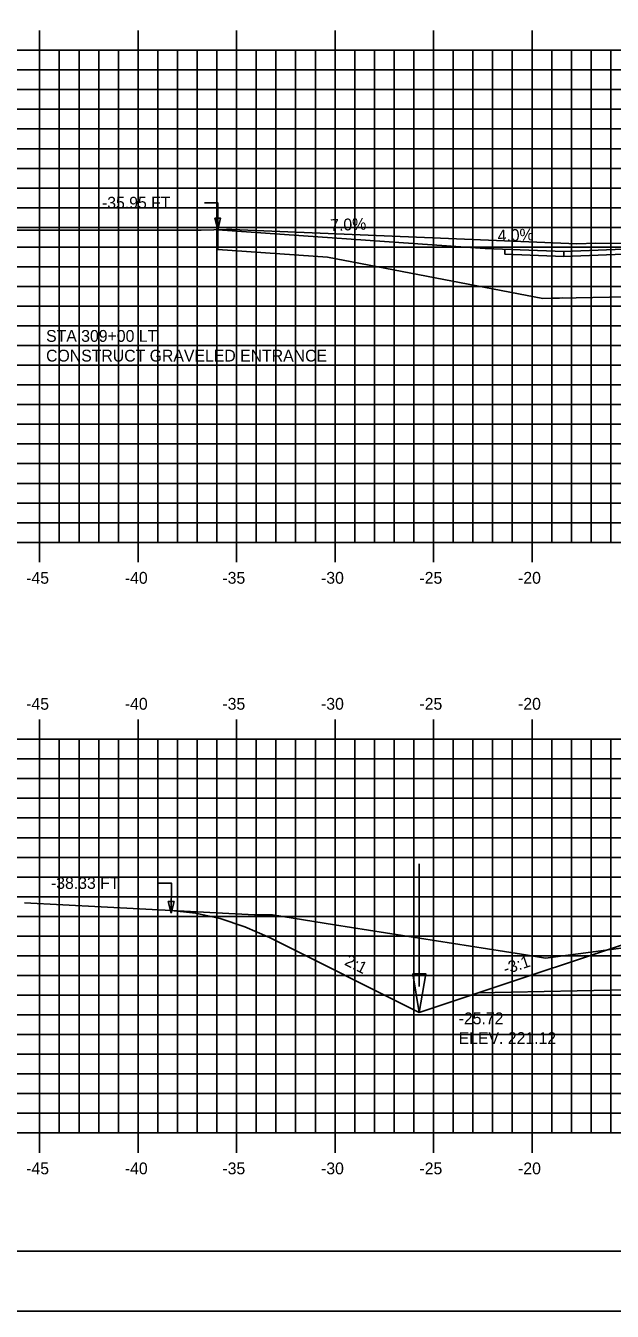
# Model space of a CAD drawing. Extents: x 1137876 to 1138046, y 608981 to 609091.
# Drawn here: x 1137913.5 to 1137943.2, y 608981.3 to 609046.6 of the extents above; entities that cross this region are included whole.
import ezdxf

# ---------------------------------------------------------------- set-up
doc = ezdxf.new("R2010")
doc.units = 0
for name, color, linetype in [('ANNOTATION', 7, 'Continuous'), ('BORDER', 7, 'Continuous'), ('D_Drainage_Ditch_Line', 7, 'Continuous'), ('D_Roadway_Edge_Shoulder', 7, 'Continuous'), ('D_Roadway_SlopeLines', 7, 'Continuous'), ('D_Roadway_SubGrade', 7, 'Continuous'), ('D_Text_Standard', 7, 'Continuous'), ('H_V ANNOTATION', 7, 'Continuous'), ('MAJOR', 7, 'Continuous'), ('MINOR', 7, 'Continuous'), ('PLOT BOUNDARY', 7, 'Continuous'), ('S_Roadway_Centerline', 7, 'Continuous')]:
    doc.layers.add(name, color=color, linetype=linetype)

msp = doc.modelspace()

# ---------------------------------------------------------------- linework, layer by layer
msp.add_lwpolyline([(1137920.838, 609001.638), (1137922.088, 609001.503), (1137923.338, 609001.228), (1137924.588, 609000.813), (1137925.838, 609000.258), (1137933.441, 608996.457), (1137936.441, 608997.457), (1137944.165, 609000.031), (1137944.166, 609000.031), (1137948.166, 609000.191), (1137959.166, 609000.411), (1137970.166, 609000.191), (1137977.166, 608999.911), (1137984.698, 608997.4), (1137989.882, 608995.673), (1137996.551, 608999.007), (1137997.801, 608999.558), (1137999.051, 608999.962), (1138000.301, 609000.217), (1138001.551, 609000.325)])
at = {"layer": 'ANNOTATION'}
for p, q in [((1137923.214, 609036.215), (1137923.214, 609035.215)), ((1137923.214, 609035.215), (1137928.788, 609034.825)), ((1137940.788, 609035.105), (1137936.788, 609035.265)), ((1137940.788, 609034.855), (1137937.79, 609034.975))]:
    msp.add_line(p, q, dxfattribs=at)
for points in [[(1137936.788, 609035.265), (1137935.788, 609035.335), (1137923.214, 609036.215)], [(1137940.722, 609032.751), (1137939.722, 609032.731), (1137928.788, 609034.825)]]:
    msp.add_lwpolyline(points, dxfattribs=at)
at = {"layer": 'BORDER'}
msp.add_lwpolyline([(1137884.166, 608984.335), (1138044.166, 608984.335), (1138044.166, 609089.335), (1137884.166, 609089.335)], close=True, dxfattribs=at)
at = {"layer": 'D_Drainage_Ditch_Line'}
msp.add_line((1137933.441, 608997.769), (1137933.442, 609004.012), dxfattribs=at)
msp.add_lwpolyline([(1137933.113, 608998.425), (1137933.769, 608998.425), (1137933.441, 608996.457)], close=True, dxfattribs=at)
at = {"layer": 'D_Roadway_Edge_Shoulder'}
msp.add_lwpolyline([(1137948.166, 609035.4), (1137940.788, 609035.105), (1137940.788, 609034.855), (1137948.166, 609035.15)], close=True, dxfattribs=at)
at = {"layer": 'D_Roadway_SlopeLines'}
msp.add_line((1137937.79, 609034.975), (1137937.79, 609035.225), dxfattribs=at)
for points in [[(1137933.441, 608996.457), (1137925.838, 609000.258), (1137924.588, 609000.813), (1137923.338, 609001.228), (1137922.088, 609001.503), (1137920.838, 609001.638)], [(1137936.441, 608997.457), (1137933.441, 608996.457)]]:
    msp.add_lwpolyline(points, dxfattribs=at)
at = {"layer": 'D_Roadway_SubGrade'}
msp.add_lwpolyline([(1137939.722, 609032.731), (1137948.166, 609032.9), (1137948.166, 609034.983), (1137948.166, 609035.15), (1137940.788, 609034.855), (1137940.788, 609035.105), (1137940.787, 609035.105), (1137940.787, 609035.105)], dxfattribs=at)
msp.add_lwpolyline([(1137948.166, 608999.774), (1137948.166, 608999.941), (1137944.166, 608999.781), (1137944.166, 609000.031), (1137944.165, 609000.031), (1137936.441, 608997.457), (1137948.166, 608997.691)], close=True, dxfattribs=at)
at = {"layer": 'D_Text_Standard'}
for points in [[(1137923.214, 609036.215), (1137923.209, 609037.591), (1137922.529, 609037.591)], [(1137920.838, 609001.508), (1137920.855, 609003.032), (1137920.175, 609003.032)]]:
    msp.add_lwpolyline(points, dxfattribs=at)
for points in [[(1137923.214, 609036.215), (1137923.066, 609036.797), (1137923.357, 609036.798)], [(1137920.838, 609001.508), (1137920.699, 609002.092), (1137920.99, 609002.089)]]:
    msp.add_lwpolyline(points, close=True, dxfattribs=at)
at = {"layer": 'MAJOR'}
for p, q in [((1137914.166, 609046.337), (1137914.166, 609045.335)), ((1137919.166, 609046.337), (1137919.166, 609045.335)), ((1137924.166, 609046.337), (1137924.166, 609045.335)), ((1137929.166, 609046.337), (1137929.166, 609045.335)), ((1137934.166, 609046.337), (1137934.166, 609045.335)), ((1137939.166, 609046.337), (1137939.166, 609045.335)), ((1137889.166, 609045.335), (1138029.166, 609045.335)), ((1137889.166, 609045.335), (1138029.166, 609045.335)), ((1137914.166, 609020.335), (1137914.166, 609045.335)), ((1137919.166, 609020.335), (1137919.166, 609045.335)), ((1137924.166, 609020.335), (1137924.166, 609045.335)), ((1137929.166, 609020.335), (1137929.166, 609045.335)), ((1137934.166, 609020.335), (1137934.166, 609045.335)), ((1137939.166, 609020.335), (1137939.166, 609045.335)), ((1137889.166, 609040.335), (1138029.166, 609040.335)), ((1137889.166, 609035.335), (1138029.166, 609035.335)), ((1137889.166, 609030.335), (1138029.166, 609030.335)), ((1137889.166, 609025.335), (1138029.166, 609025.335)), ((1137889.166, 609020.335), (1138029.166, 609020.335)), ((1137889.166, 609020.335), (1138029.166, 609020.335)), ((1137914.166, 609019.333), (1137914.166, 609020.335)), ((1137919.166, 609019.333), (1137919.166, 609020.335)), ((1137924.166, 609019.333), (1137924.166, 609020.335)), ((1137929.166, 609019.333), (1137929.166, 609020.335)), ((1137934.166, 609019.333), (1137934.166, 609020.335)), ((1137939.166, 609019.333), (1137939.166, 609020.335)), ((1137914.166, 609011.337), (1137914.166, 609010.335)), ((1137919.166, 609011.337), (1137919.166, 609010.335)), ((1137924.166, 609011.337), (1137924.166, 609010.335)), ((1137929.166, 609011.337), (1137929.166, 609010.335)), ((1137934.166, 609011.337), (1137934.166, 609010.335)), ((1137939.166, 609011.337), (1137939.166, 609010.335)), ((1137889.166, 609010.335), (1138029.166, 609010.335)), ((1137889.166, 609010.335), (1138029.166, 609010.335)), ((1137914.166, 608990.335), (1137914.166, 609010.335)), ((1137919.166, 608990.335), (1137919.166, 609010.335)), ((1137924.166, 608990.335), (1137924.166, 609010.335)), ((1137929.166, 608990.335), (1137929.166, 609010.335)), ((1137934.166, 608990.335), (1137934.166, 609010.335)), ((1137939.166, 608990.335), (1137939.166, 609010.335)), ((1137889.166, 609005.335), (1138029.166, 609005.335)), ((1137889.166, 609000.335), (1138029.166, 609000.335)), ((1137889.166, 608995.335), (1138029.166, 608995.335)), ((1137889.166, 608990.335), (1138029.166, 608990.335)), ((1137889.166, 608990.335), (1138029.166, 608990.335)), ((1137914.166, 608989.333), (1137914.166, 608990.335)), ((1137919.166, 608989.333), (1137919.166, 608990.335)), ((1137924.166, 608989.333), (1137924.166, 608990.335)), ((1137929.166, 608989.333), (1137929.166, 608990.335)), ((1137934.166, 608989.333), (1137934.166, 608990.335)), ((1137939.166, 608989.333), (1137939.166, 608990.335))]:
    msp.add_line(p, q, dxfattribs=at)
at = {"layer": 'MINOR'}
for p, q in [((1137915.166, 609020.335), (1137915.166, 609045.335)), ((1137916.166, 609020.335), (1137916.166, 609045.335)), ((1137917.166, 609020.335), (1137917.166, 609045.335)), ((1137918.166, 609020.335), (1137918.166, 609045.335)), ((1137920.166, 609020.335), (1137920.166, 609045.335)), ((1137921.166, 609020.335), (1137921.166, 609045.335)), ((1137922.166, 609020.335), (1137922.166, 609045.335)), ((1137923.166, 609020.335), (1137923.166, 609045.335)), ((1137925.166, 609020.335), (1137925.166, 609045.335)), ((1137926.166, 609020.335), (1137926.166, 609045.335)), ((1137927.166, 609020.335), (1137927.166, 609045.335)), ((1137928.166, 609020.335), (1137928.166, 609045.335)), ((1137930.166, 609020.335), (1137930.166, 609045.335)), ((1137931.166, 609020.335), (1137931.166, 609045.335)), ((1137932.166, 609020.335), (1137932.166, 609045.335)), ((1137933.166, 609020.335), (1137933.166, 609045.335)), ((1137935.166, 609020.335), (1137935.166, 609045.335)), ((1137936.166, 609020.335), (1137936.166, 609045.335)), ((1137937.166, 609020.335), (1137937.166, 609045.335)), ((1137938.166, 609020.335), (1137938.166, 609045.335)), ((1137940.166, 609020.335), (1137940.166, 609045.335)), ((1137941.166, 609020.335), (1137941.166, 609045.335)), ((1137942.166, 609020.335), (1137942.166, 609045.335)), ((1137943.166, 609020.335), (1137943.166, 609045.335)), ((1137889.166, 609044.335), (1138029.166, 609044.335)), ((1137889.166, 609043.335), (1138029.166, 609043.335)), ((1137889.166, 609042.335), (1138029.166, 609042.335)), ((1137889.166, 609041.335), (1138029.166, 609041.335)), ((1137889.166, 609039.335), (1138029.166, 609039.335)), ((1137889.166, 609038.335), (1138029.166, 609038.335)), ((1137889.166, 609037.335), (1138029.166, 609037.335)), ((1137889.166, 609036.335), (1138029.166, 609036.335)), ((1137889.166, 609034.335), (1138029.166, 609034.335)), ((1137889.166, 609033.335), (1138029.166, 609033.335)), ((1137889.166, 609032.335), (1138029.166, 609032.335)), ((1137889.166, 609031.335), (1138029.166, 609031.335)), ((1137889.166, 609029.335), (1138029.166, 609029.335)), ((1137889.166, 609028.335), (1138029.166, 609028.335)), ((1137889.166, 609027.335), (1138029.166, 609027.335)), ((1137889.166, 609026.335), (1138029.166, 609026.335)), ((1137889.166, 609024.335), (1138029.166, 609024.335)), ((1137889.166, 609023.335), (1138029.166, 609023.335)), ((1137889.166, 609022.335), (1138029.166, 609022.335)), ((1137889.166, 609021.335), (1138029.166, 609021.335)), ((1137915.166, 608990.335), (1137915.166, 609010.335)), ((1137916.166, 608990.335), (1137916.166, 609010.335)), ((1137917.166, 608990.335), (1137917.166, 609010.335)), ((1137918.166, 608990.335), (1137918.166, 609010.335)), ((1137920.166, 608990.335), (1137920.166, 609010.335)), ((1137921.166, 608990.335), (1137921.166, 609010.335)), ((1137922.166, 608990.335), (1137922.166, 609010.335)), ((1137923.166, 608990.335), (1137923.166, 609010.335)), ((1137925.166, 608990.335), (1137925.166, 609010.335)), ((1137926.166, 608990.335), (1137926.166, 609010.335)), ((1137927.166, 608990.335), (1137927.166, 609010.335)), ((1137928.166, 608990.335), (1137928.166, 609010.335)), ((1137930.166, 608990.335), (1137930.166, 609010.335)), ((1137931.166, 608990.335), (1137931.166, 609010.335)), ((1137932.166, 608990.335), (1137932.166, 609010.335)), ((1137933.166, 608990.335), (1137933.166, 609010.335)), ((1137935.166, 608990.335), (1137935.166, 609010.335)), ((1137936.166, 608990.335), (1137936.166, 609010.335)), ((1137937.166, 608990.335), (1137937.166, 609010.335)), ((1137938.166, 608990.335), (1137938.166, 609010.335)), ((1137940.166, 608990.335), (1137940.166, 609010.335)), ((1137941.166, 608990.335), (1137941.166, 609010.335)), ((1137942.166, 608990.335), (1137942.166, 609010.335)), ((1137943.166, 608990.335), (1137943.166, 609010.335)), ((1137889.166, 609009.335), (1138029.166, 609009.335)), ((1137889.166, 609008.335), (1138029.166, 609008.335)), ((1137889.166, 609007.335), (1138029.166, 609007.335)), ((1137889.166, 609006.335), (1138029.166, 609006.335)), ((1137889.166, 609004.335), (1138029.166, 609004.335)), ((1137889.166, 609003.335), (1138029.166, 609003.335)), ((1137889.166, 609002.335), (1138029.166, 609002.335)), ((1137889.166, 609001.335), (1138029.166, 609001.335)), ((1137889.166, 608999.335), (1138029.166, 608999.335)), ((1137889.166, 608998.335), (1138029.166, 608998.335)), ((1137889.166, 608997.335), (1138029.166, 608997.335)), ((1137889.166, 608996.335), (1138029.166, 608996.335)), ((1137889.166, 608994.335), (1138029.166, 608994.335)), ((1137889.166, 608993.335), (1138029.166, 608993.335)), ((1137889.166, 608992.335), (1138029.166, 608992.335)), ((1137889.166, 608991.335), (1138029.166, 608991.335))]:
    msp.add_line(p, q, dxfattribs=at)
at = {"layer": 'PLOT BOUNDARY'}
msp.add_lwpolyline([(1137876.073, 608981.276), (1138046.073, 608981.276), (1138046.073, 609091.276), (1137876.073, 609091.276)], close=True, dxfattribs=at)
at = {"layer": 'S_Roadway_Centerline'}
for points in [[(1137889.166, 609035.87), (1137897.769, 609036.097), (1137903.847, 609036.195), (1137922.362, 609036.192), (1137923.647, 609036.227), (1137923.926, 609036.236), (1137941.45, 609035.497), (1137942.404, 609035.527), (1137948.191, 609035.512), (1137948.754, 609035.58), (1137958.379, 609035.602), (1137959.886, 609035.609), (1137962.573, 609035.562), (1137971.217, 609035.463), (1137975.089, 609034.703), (1137976.201, 609034.668), (1137977.29, 609034.412), (1137981.28, 609033.073), (1137986.631, 609031.589), (1137994.165, 609030.324)], [(1137913.402, 609002.025), (1137925.071, 609001.418), (1137925.992, 609001.418), (1137929.134, 609000.907), (1137938.63, 608999.416), (1137939.85, 608999.214), (1137944.822, 608999.879), (1137945.703, 608999.951), (1137945.946, 608999.984), (1137946.358, 608999.993), (1137948.391, 609000.159), (1137957.12, 609000.265), (1137958.769, 609000.269), (1137960.476, 609000.25), (1137970.117, 609000.341), (1137972.353, 609000.179), (1137972.977, 609000.115), (1137973.526, 608999.958), (1137975.073, 608999.475), (1137976.852, 608999.609), (1137978.118, 608999.683), (1137980.358, 609000.082), (1137983.958, 609000.205), (1137988.409, 609000.056)]]:
    msp.add_lwpolyline(points, dxfattribs=at)

# ---------------------------------------------------------------- texts
at = {"layer": 'ANNOTATION'}
for s, rotation, p in [('7.0%', 2.29061, (1137928.933, 609036.149)), ('4.0%', 2.29061, (1137937.431, 609035.612)), ('2:1', 333.43495, (1137929.607, 608998.892)), ('-3:1', 18.43482, (1137937.82, 608998.37))]:
    msp.add_text(s, height=0.6, rotation=rotation, dxfattribs=at).set_placement(p)
for s, p in [('STA 309+00 LT', (1137914.494, 609030.524)), ('CONSTRUCT GRAVELED ENTRANCE', (1137914.494, 609029.522))]:
    msp.add_text(s, height=0.6, dxfattribs=at).set_placement(p)
at = {"layer": 'D_Text_Standard'}
for s, p in [('-35.95 FT', (1137917.331, 609037.291)), ('-38.33 FT', (1137914.742, 609002.732)), ('-25.72', (1137935.441, 608995.857)), ('ELEV. 221.12', (1137935.441, 608994.855))]:
    msp.add_text(s, height=0.6, dxfattribs=at).set_placement(p)
at = {"layer": 'H_V ANNOTATION'}
for s, p in [('-45', (1137913.484, 609018.235)), ('-40', (1137918.492, 609018.235)), ('-35', (1137923.446, 609018.235)), ('-30', (1137928.454, 609018.235)), ('-25', (1137933.451, 609018.235)), ('-20', (1137938.459, 609018.235)), ('-45', (1137913.484, 609011.835)), ('-40', (1137918.492, 609011.835)), ('-35', (1137923.446, 609011.835)), ('-30', (1137928.454, 609011.835)), ('-25', (1137933.451, 609011.835)), ('-20', (1137938.459, 609011.835)), ('-45', (1137913.484, 608988.235)), ('-40', (1137918.492, 608988.235)), ('-35', (1137923.446, 608988.235)), ('-30', (1137928.454, 608988.235)), ('-25', (1137933.451, 608988.235)), ('-20', (1137938.459, 608988.235))]:
    msp.add_text(s, height=0.6, dxfattribs=at).set_placement(p)

doc.saveas('drawing.dxf')
